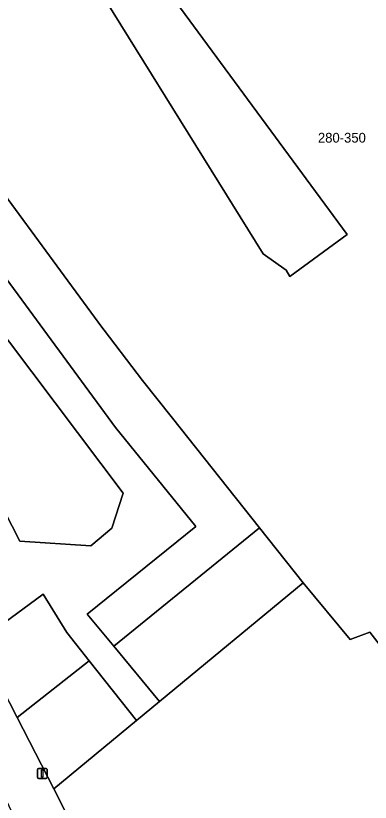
# Model space of a CAD drawing. Extents: x 161087 to 161926, y 382572 to 383873.
# Drawn here: x 161780.2 to 161816.5, y 382874.6 to 382955.3 of the extents above; entities that cross this region are included whole.
import ezdxf

# ---------------------------------------------------------------- set-up
doc = ezdxf.new("R2010")
doc.units = 0
for name, color, linetype in [('IMGEO_Erf', 7, 'Continuous'), ('IMGEO_Groenvoorziening', 7, 'Continuous'), ('IMGEO_Hek', 7, 'Continuous'), ('IMGEO_Lichtmast', 7, 'Continuous'), ('IMGEO_Pand', 7, 'Continuous'), ('IMGEO_Pand_nummerreeks', 7, 'Continuous'), ('IMGEO_Parkeervlak_gesloten', 7, 'Continuous'), ('IMGEO_Rijbaan_lokaal_gesloten', 7, 'Continuous'), ('IMGEO_Rijbaan_lokaal_open', 7, 'Continuous')]:
    doc.layers.add(name, color=color, linetype=linetype)

msp = doc.modelspace()

# ---------------------------------------------------------------- linework, layer by layer
at = {"layer": 'IMGEO_Erf'}
msp.add_lwpolyline([(161784.088, 382965.443), (161805.553, 382930.844), (161807.905, 382929.167), (161808.285, 382928.523), (161814.151, 382932.831), (161796.626, 382956.694)], dxfattribs=at)
at = {"layer": 'IMGEO_Groenvoorziening'}
for points in [[(161809.669, 382897.124), (161805.197, 382902.753), (161790.275, 382890.622), (161794.956, 382884.96)], [(161787.763, 382889.132), (161780.366, 382883.342), (161784.138, 382876.015), (161792.612, 382883.021)]]:
    msp.add_lwpolyline(points, close=True, dxfattribs=at)
at = {"layer": 'IMGEO_Hek'}
msp.add_lwpolyline([(161771.091, 382901.359), (161773.236, 382897.192), (161776.376, 382891.093), (161780.366, 382883.342), (161784.138, 382876.015)], dxfattribs=at)
at = {"layer": 'IMGEO_Lichtmast'}
for p, q in [((161782.551, 382878.088), (161783.341, 382878.088)), ((161783.341, 382878.088), (161782.551, 382878.088)), ((161782.451, 382877.188), (161782.451, 382877.988)), ((161782.451, 382877.988), (161782.451, 382877.188)), ((161783.441, 382877.988), (161783.441, 382877.188)), ((161783.441, 382877.188), (161783.441, 382877.988)), ((161783.341, 382877.088), (161782.551, 382877.088)), ((161782.551, 382877.088), (161783.341, 382877.088))]:
    msp.add_line(p, q, dxfattribs=at)
msp.add_lwpolyline([(161782.871, 382877.963), (161783.021, 382877.963), (161783.021, 382877.213), (161782.871, 382877.213), (161782.871, 382877.963)], dxfattribs=at)
for centre, start, end in [((161782.551, 382877.988), 90, 180), ((161782.551, 382877.988), 90, 180), ((161783.341, 382877.988), 0, 90), ((161783.341, 382877.988), 360, 90), ((161782.551, 382877.188), 180, 270), ((161782.551, 382877.188), 180, 270), ((161783.341, 382877.188), 270, 0), ((161783.341, 382877.188), 270, 0)]:
    msp.add_arc(centre, 0.1, start, end, dxfattribs=at)
at = {"layer": 'IMGEO_Pand'}
for points in [[(161775.734, 382974.185), (161763.844, 382953.981), (161765.214, 382952.918), (161770.116, 382949.117), (161772.375, 382946.039), (161774.058, 382943.746), (161788.662, 382923.846), (161788.735, 382923.75), (161793.197, 382917.858), (161796.266, 382913.995), (161805.197, 382902.753), (161809.669, 382897.124), (161814.47, 382891.319), (161816.481, 382892.083), (161825.263, 382880.78)], [(161796.626, 382956.694), (161814.151, 382932.831), (161808.285, 382928.523), (161807.905, 382929.167), (161805.553, 382930.844), (161784.088, 382965.443)], [(161825.263, 382880.78), (161816.481, 382892.083), (161814.47, 382891.319), (161809.669, 382897.124), (161794.956, 382884.96), (161792.612, 382883.021), (161784.138, 382876.015), (161789.672, 382865.069)]]:
    msp.add_lwpolyline(points, dxfattribs=at)
at = {"layer": 'IMGEO_Parkeervlak_gesloten'}
for points in [[(161796.266, 382913.995), (161793.197, 382917.858), (161788.735, 382923.75), (161788.662, 382923.846), (161774.058, 382943.746), (161770.001, 382940.906), (161790.437, 382913.051), (161798.678, 382902.905), (161787.541, 382893.928), (161790.275, 382890.622), (161805.197, 382902.753)], [(161787.763, 382889.132), (161785.452, 382892.043), (161783.036, 382895.982), (161776.376, 382891.093), (161780.366, 382883.342)]]:
    msp.add_lwpolyline(points, close=True, dxfattribs=at)
msp.add_lwpolyline([(161765.074, 382931.859), (161780.649, 382901.401), (161787.923, 382900.93), (161790.084, 382902.743), (161791.248, 382906.325), (161770.22, 382934.243)], dxfattribs=at)
at = {"layer": 'IMGEO_Rijbaan_lokaal_gesloten'}
msp.add_lwpolyline([(161770.001, 382940.906), (161768.956, 382940.174), (161767.325, 382942.503), (161772.375, 382946.039), (161770.116, 382949.117), (161765.214, 382952.918), (161763.844, 382953.981), (161760.245, 382948), (161757.765, 382943.88), (161756.155, 382941.205), (161761, 382931.897), (161775.431, 382903.801), (161773.236, 382897.192), (161776.376, 382891.093), (161783.036, 382895.982), (161785.452, 382892.043), (161787.763, 382889.132), (161792.612, 382883.021), (161794.956, 382884.96), (161790.275, 382890.622), (161787.541, 382893.928), (161798.678, 382902.905), (161790.437, 382913.051)], close=True, dxfattribs=at)
msp.add_lwpolyline([(161770.22, 382934.243), (161791.248, 382906.325), (161790.084, 382902.743), (161787.923, 382900.93), (161780.649, 382901.401), (161765.074, 382931.859)], dxfattribs=at)
at = {"layer": 'IMGEO_Rijbaan_lokaal_open'}
msp.add_lwpolyline([(161789.672, 382865.069), (161784.138, 382876.015), (161780.366, 382883.342), (161776.376, 382891.093), (161773.236, 382897.192), (161771.091, 382901.359), (161759.078, 382924.694), (161754.557, 382922.389), (161762.135, 382908.027), (161763.926, 382904.529), (161765.524, 382901.027), (161770.996, 382891.041), (161776.413, 382880.664), (161778.973, 382875.402), (161781.64, 382869.915)], dxfattribs=at)

# ---------------------------------------------------------------- texts
at = {"layer": 'IMGEO_Pand_nummerreeks'}
msp.add_text('280-350', height=1, dxfattribs=at).set_placement((161811.167, 382942.25))

doc.saveas('drawing.dxf')
